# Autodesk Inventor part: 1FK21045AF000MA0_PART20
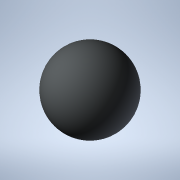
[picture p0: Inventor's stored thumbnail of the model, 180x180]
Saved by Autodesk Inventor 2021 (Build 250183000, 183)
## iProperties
Created: 2025-04
Part Number: 1FK21045AF000MA0_PART20
Material: Generic
Catalog Web Link: www.3dfindit.com
Description: -Servo synchronous motor
Document SubType Name: Modeling
Designer: psAdmin
Mass: 0.137258 g
Surface Area: 1.2868 cm^2
Volume: 0.137258 cm^3
Density: 1 g/cm^3
Appearance: PSOLRGB-212-217-219
Category: PARTsolutions
Title: 1FK21045AF000MA0_PART20
Author: Cadenas PARTsolutions
Comments: Servo synchronous motor
Sending System: PARTsolutions
Preprocessor: ST-DEVELOPER v19.3
PSOL_IDENT_0: {$CADENAS_DATA/23d-libs/siemens_ag/_cat_/8b/0a/1fk21045af000ma0.prj},216 {VTYP=3D},{NB=1FK21045AF000
PSOL_IDENT_1: MA0_PART20},{LINA=1FK21045AF000MA0_PART20},{NN=1FK21045AF000MA0_PART20},{NOPRJ=TRUE},{DATE=19.08.202
PSOL_IDENT_2: 5 14:00:48},{GEOMDATE=30.07.2025 02:00:28},{VERSION=},{LINEID=10},{WBVAR=},{WBNUMERIC=}  {NB=1FK2104
PSOL_IDENT_3: 5AF000MA0_PART20},{LINA=1FK21045AF000MA0_PART20},{KT=DUMMY},{PREVIEW=../../../_pool_/a9/69/p_d211_xx
PSOL_IDENT_4: _00818j.png},{DESCSHORT=SIMOTICS S-1FK2 HD, SINAMICS S210 3AC 400V-480V, 2.4 Nm, 3000 rpm},{DESCLONG=
PSOL_IDENT_5: SIMOTICS S-1FK2 HD servo motor M0=2.4 Nm; PN = 0.75 kW at nN=3000 rpm (380-480 V); PN = 0.375 kW at
PSOL_IDENT_6: nN=1500 rpm (200-240 V); degree of protection IP64; cylindrical shaft D19x40mm; absolute encoder 22-
PSOL_IDENT_7: bit + 12-bit multiturn (encoder AM22DQC); with OCC interface; plug size M17, rotatable; SIMOTICS S-1
PSOL_IDENT_8: FK2 servomotorfor a wide range of uses in industrial environments. SIMOTICS S‑1FK2 servomotors are c
PSOL_IDENT_9: ompact synchronous motors with a high dynamic performance that set themselves apart as a result of t
PSOL_IDENT_10: heir high power density, degree of protection and overload capability. The motors are available in t
PSOL_IDENT_11: wo variants: as High Dynamic variant (highest dynamic performance as a result of the low intrinsic m
PSOL_IDENT_12: oment of inertia for applications demanding a high dynamic performance with low moved masses) - and
PSOL_IDENT_13: as Compact variant (precise and stable closed-loop control for medium up to large moved masses as a
PSOL_IDENT_14: result of a medium intrinsic moment of inertia). SIMOTICSS‑1FK2 servomotors fully exploit their stre
PSOL_IDENT_15: ngths in a system with the SINAMICSS210 frequency converter and simple connection using the one cabl
PSOL_IDENT_16: e connection (OCC). Advantages include the short control and positioning times, fast and precise cor
PSOL_IDENT_17: rection of disturbing quantities as well as stable control with a high dynamic performance. The serv
PSOL_IDENT_18: o motors can be configured to address a wide range of requirements. For example with and without hol
PSOL_IDENT_19: ding brake, IP64 or IP65 degree of protection, singleturn or multiturn absolute encoders - to name j
PSOL_IDENT_20: ust a few. Further, the servomotors are available in different shaft heights extending from 20 to 10
PSOL_IDENT_21: 0. A shaft sealing ring is available to achieve an IP65 degree of protection and for subsequent moun
PSOL_IDENT_22: ting at the motor or as spare part. SIMOTICS - the optimum motor for each and every motion control a
PSOL_IDENT_23: pplication.},{INTNO=195125050112},{SUPPLIERALTNO=1FK2104-5AF00-0MA0},{MANUID=1FK21045AF000MA0},{MANU
PSOL_IDENT_24: NAME=Siemens},{MANUTYPEDESC=Synchronous motor 1FK2-HD 2.4 NM},{AAU732=SIMOTICS},{AAO057=S-1FK2},{AAU
PSOL_IDENT_25: 734=SIMOTICS S-1FK2 HD servo motor M0=2.4 Nm; PN = 0.75 kW at nN=3000 rpm (380-480 V); PN = 0.375 kW
PSOL_IDENT_26: at nN=1500 rpm (200-240 V); degree of protection IP64; cylindrical shaft D19x40mm; absolute encoder
PSOL_IDENT_27: 22-bit + 12-bit multiturn (encoder AM22DQC); with OCC interface; plug size M17, rotatable;},{AAW338=
PSOL_IDENT_28: Synchronous motor 1FK2-HD 2.4 NM},{AAO742=SIMOTICS},{AAO663=4042948692912},{NOCUPEROU=1},{PRICEQUANT
PSOL_IDENT_29: ITY=1},{QUANTITYMIN=1},{QUANTITYINT=1},{CTN=85015100},{COO=DE},{AAO676=1FK2104-5AF00-0MA0},{AAO677=S
PSOL_IDENT_30: iemens AG},{ORDERUNIT=C62},{CONTENTUNIT=C62}
NB: 1FK21045AF000MA0_PART20
NT: Servo synchronous motor
NBSYN: $MANUID._PART20
LINA: 1FK21045AF000MA0_PART20
CATALOG: SIEMENS
PREVIEW: ../../../_pool_/a9/69/p_d211_xx_00818j.png
DESCSHORT: SIMOTICS S-1FK2 HD, SINAMICS S210 3AC 400V-480V, 2.4 Nm, 3000 rpm
DESCLONG: SIMOTICS S-1FK2 HD servo motor M0=2.4 Nm; PN = 0.75 kW at nN=3000 rpm (380-480 V); PN = 0.375 kW at nN=1500 rpm (200-240 V); degree of protection IP64; cylindri
INTNO: 195125050112
SUPPLIERALTNO: 1FK2104-5AF00-0MA0
MANUID: 1FK21045AF000MA0
MANUNAME: Siemens
MANUTYPEDESC: Synchronous motor 1FK2-HD 2.4 NM
AAU732: SIMOTICS
AAO057: S-1FK2
AAU734: SIMOTICS S-1FK2 HD servo motor M0=2.4 Nm; PN = 0.75 kW at nN=3000 rpm (380-480 V); PN = 0.375 kW at nN=1500 rpm (200-240 V); degree of protection IP64; cylindri
AAW338: Synchronous motor 1FK2-HD 2.4 NM
AAO742: SIMOTICS
AAO663: 4042948692912.0
NOCUPEROU: 1
PRICEQUANTITY: 1
QUANTITYMIN: 1
QUANTITYINT: 1
CTN: 85015100
COO: DE
ARTICLENO: 1FK21045AF000MA0_PART20
BOMINFO: 1FK21045AF000MA0_PART20
CREATOR: CADENAS GmbH
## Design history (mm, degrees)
feature "2025_04_17_15_40_42_0766"
body "Solid1"
